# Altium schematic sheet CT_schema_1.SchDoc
size 550 x 508 mm
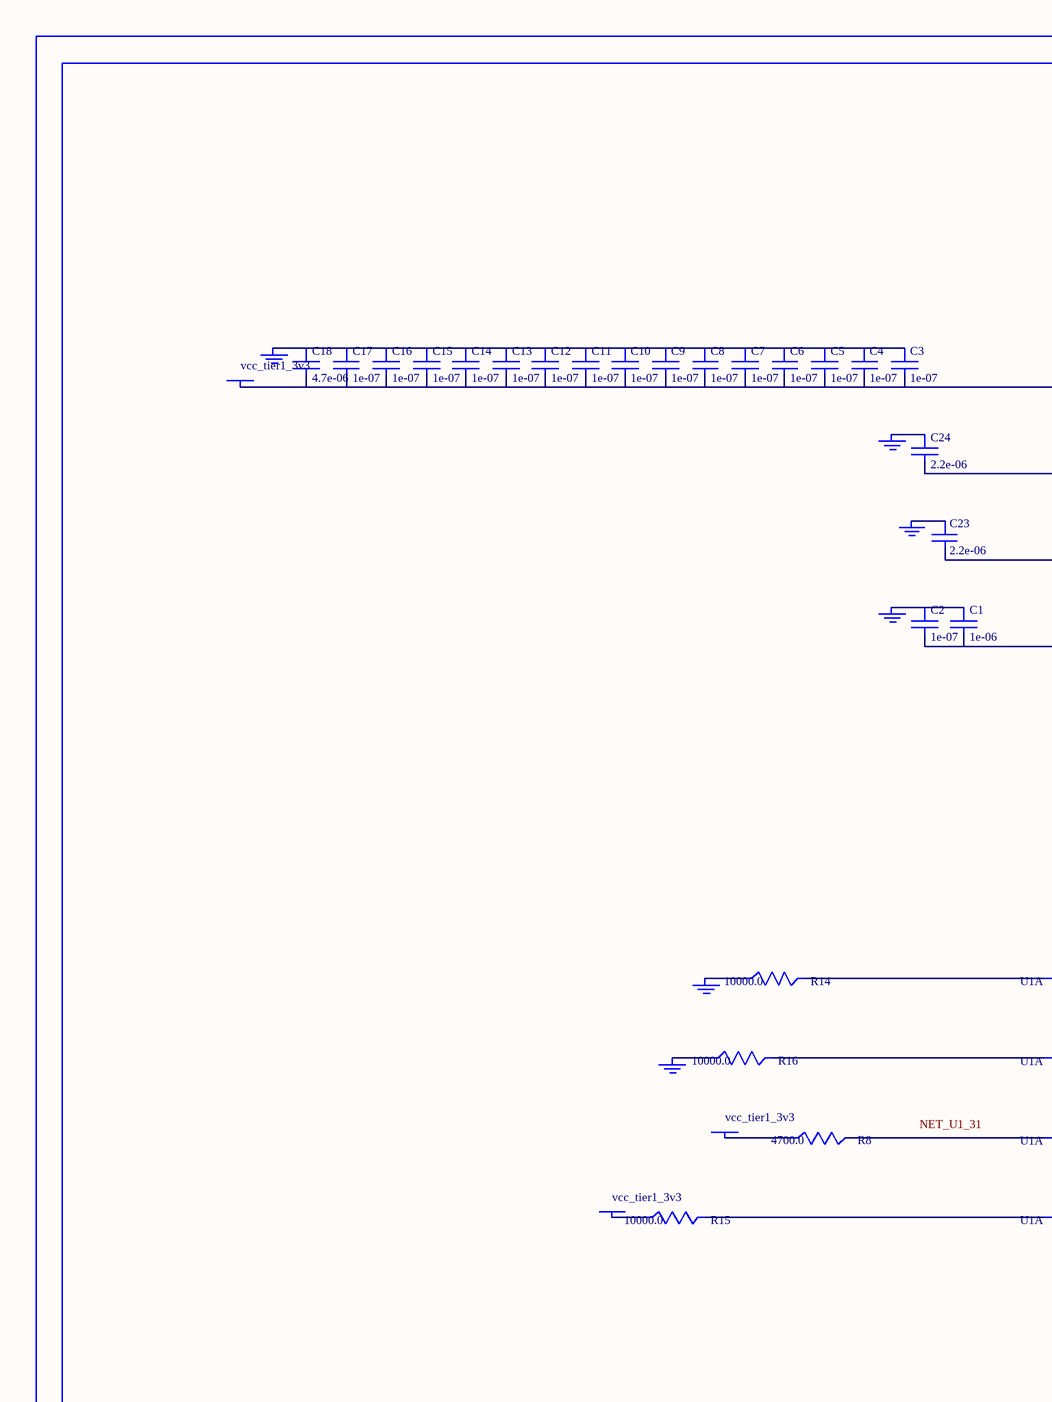
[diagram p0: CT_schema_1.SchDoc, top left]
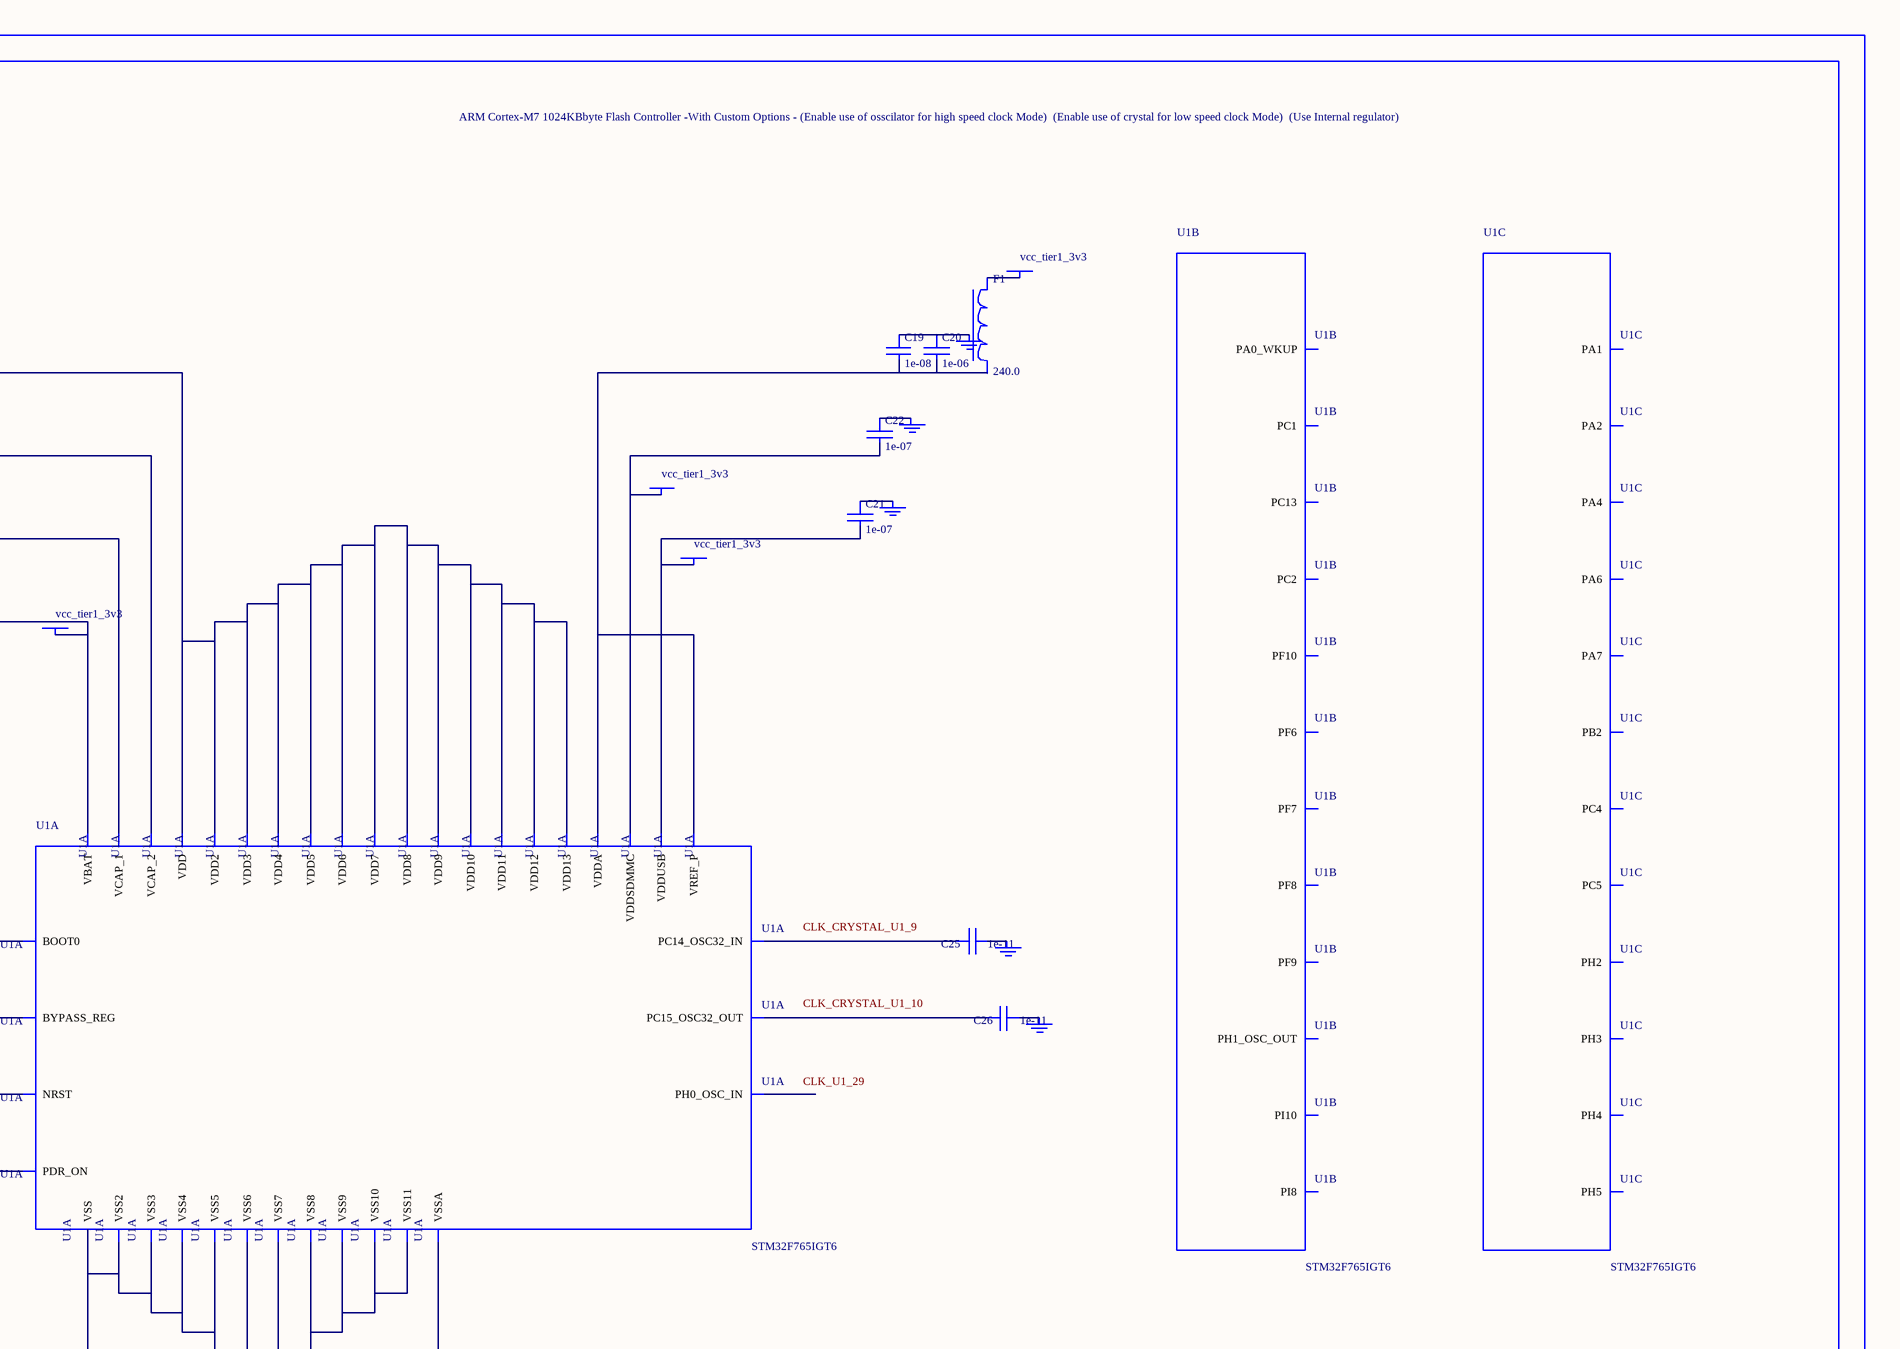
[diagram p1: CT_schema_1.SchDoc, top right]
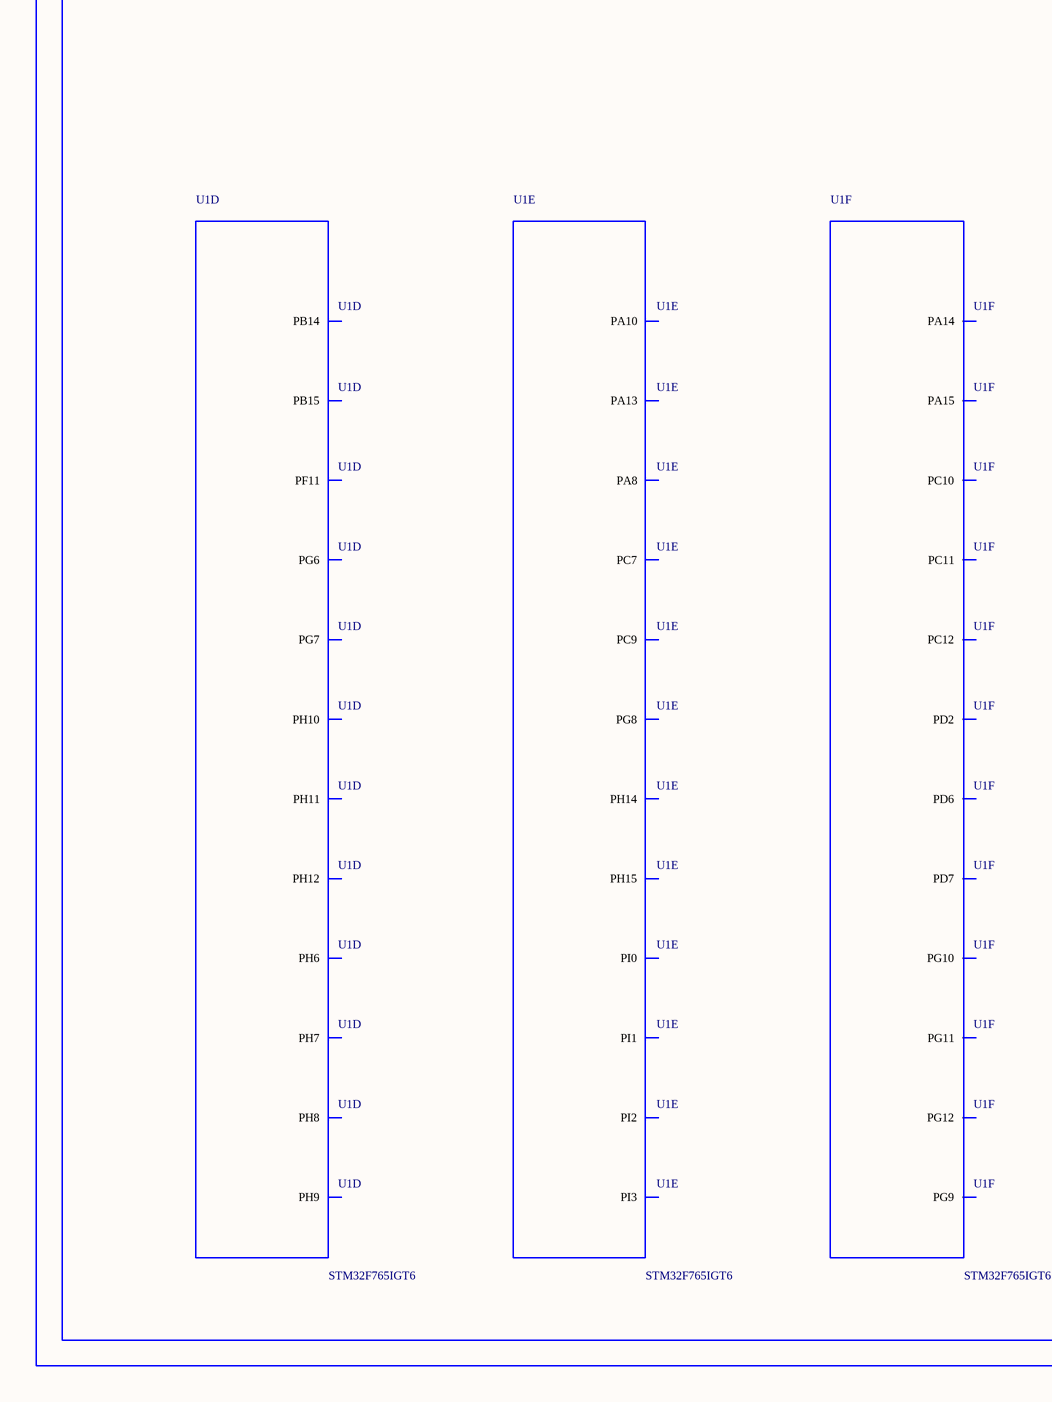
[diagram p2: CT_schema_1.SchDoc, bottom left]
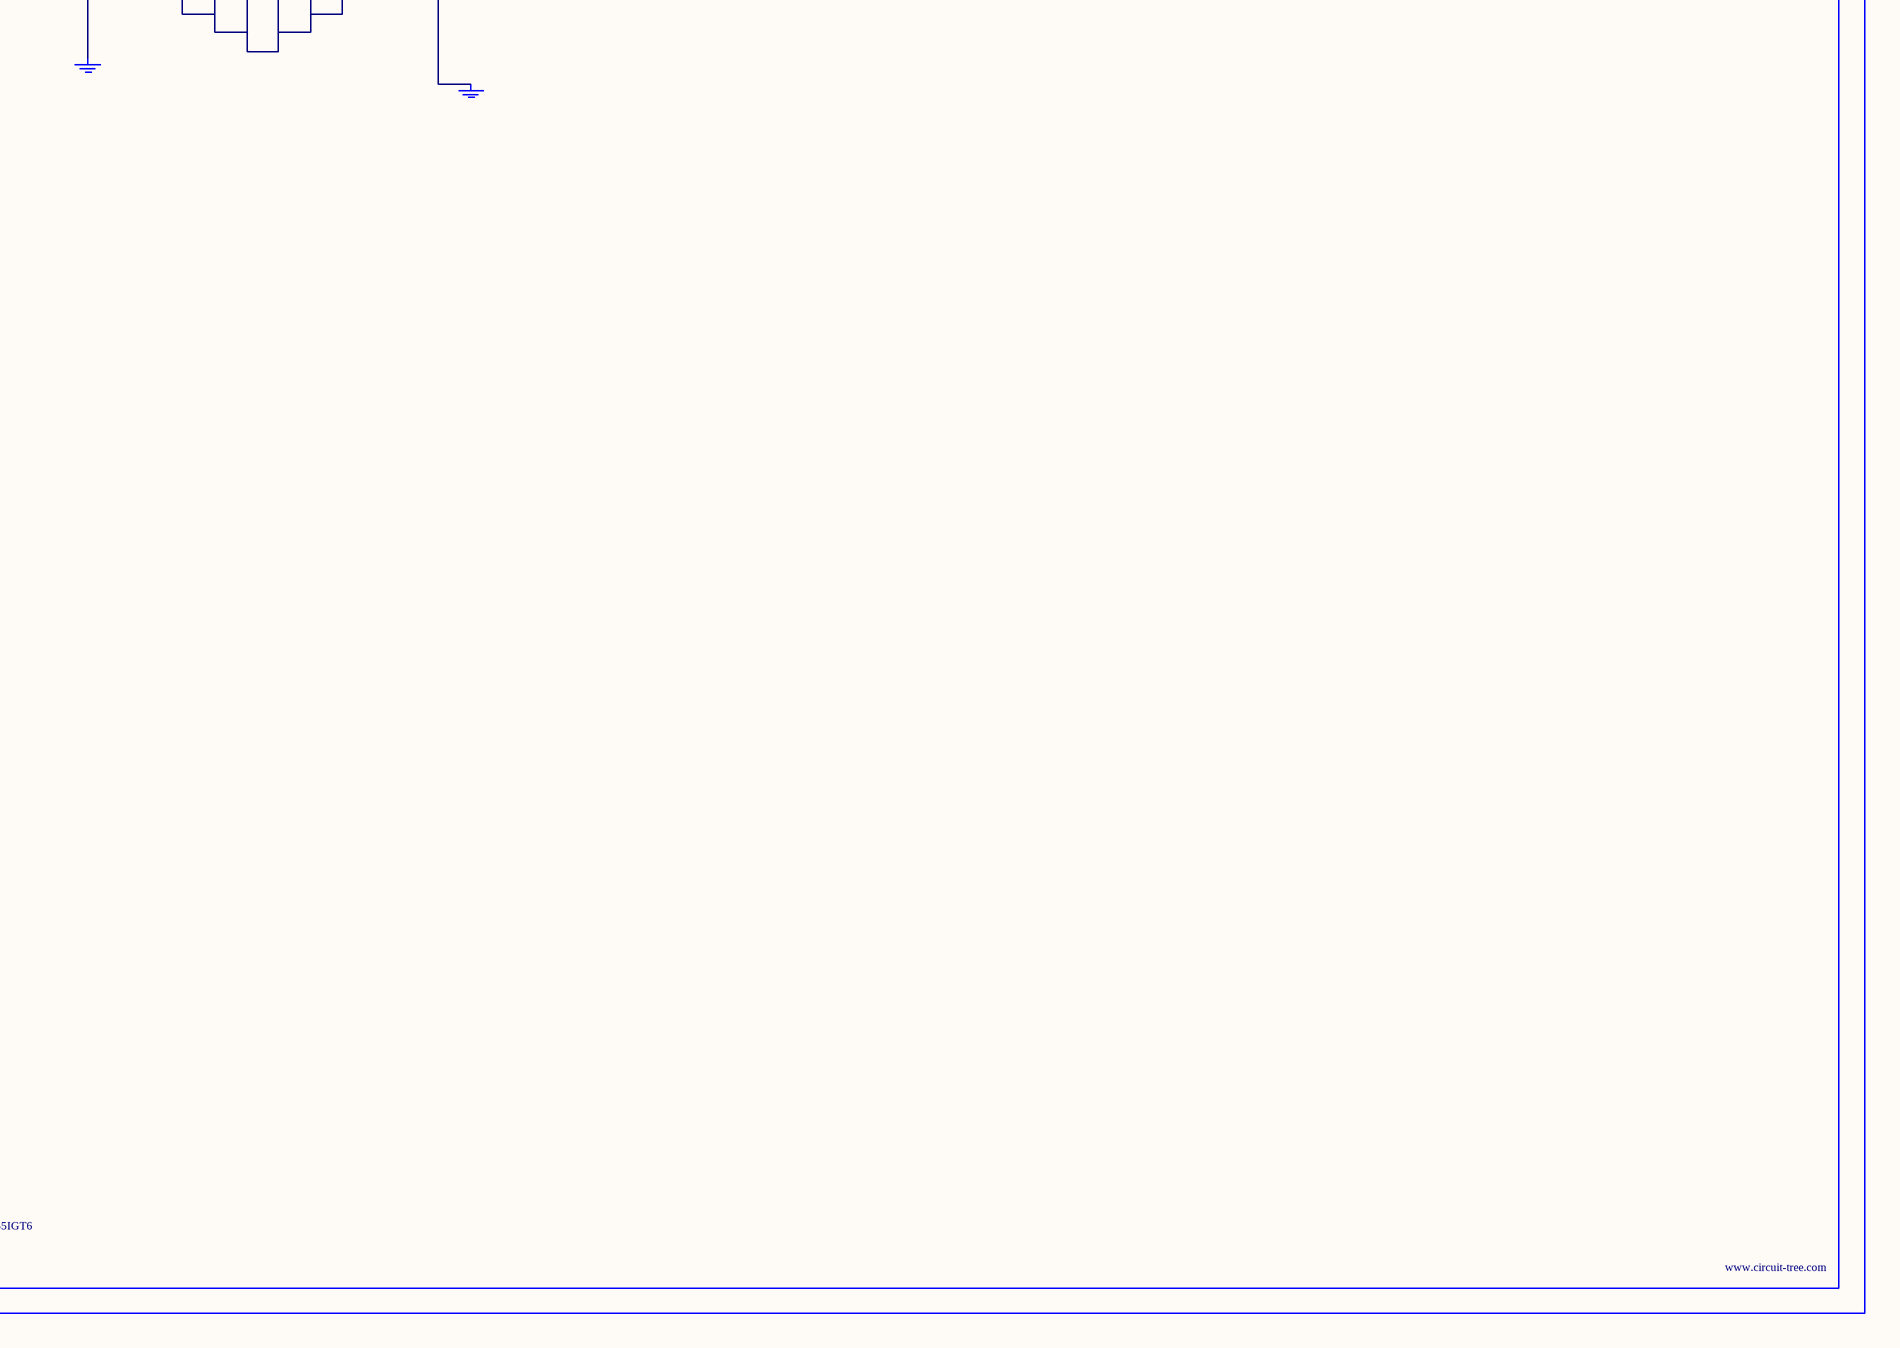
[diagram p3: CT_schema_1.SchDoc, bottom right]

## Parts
BORDER0  (no value)
C1  1e-06  [C0603]
C2  1e-07  [C0603]
C3  1e-07  [C0603]
C4  1e-07  [C0603]
C5  1e-07  [C0603]
C6  1e-07  [C0603]
C7  1e-07  [C0603]
C8  1e-07  [C0603]
C9  1e-07  [C0603]
C10  1e-07  [C0603]
C11  1e-07  [C0603]
C12  1e-07  [C0603]
C13  1e-07  [C0603]
C14  1e-07  [C0603]
C15  1e-07  [C0603]
C16  1e-07  [C0603]
C17  1e-07  [C0603]
C18  4.7e-06  [C0603]
C19  1e-08  [C0603]
C20  1e-06  [C0603]
C21  1e-07  [C0603]
C22  1e-07  [C0603]
C23  2.2e-06  [C0603]
C24  2.2e-06  [C0603]
C25  1e-11  [C0402]
C26  1e-11  [C0402]
F1  240.0  [L0603]
GND_INSTANCE_0_0  (no value)
GND_INSTANCE_0_1  (no value)
GND_INSTANCE_0_2  (no value)
GND_INSTANCE_0_3  (no value)
GND_INSTANCE_0_4  (no value)
GND_INSTANCE_0_5  (no value)
GND_INSTANCE_0_6  (no value)
GND_INSTANCE_0_7  (no value)
GND_INSTANCE_0_8  (no value)
GND_INSTANCE_0_9  (no value)
GND_INSTANCE_0_10  (no value)
GND_INSTANCE_0_11  (no value)
GND_INSTANCE_0_12  (no value)
POWER_INSTANCE_0_0  vcc_tier1_3v3
POWER_INSTANCE_0_1  vcc_tier1_3v3
POWER_INSTANCE_0_2  vcc_tier1_3v3
POWER_INSTANCE_0_3  vcc_tier1_3v3
POWER_INSTANCE_0_4  vcc_tier1_3v3
POWER_INSTANCE_0_5  vcc_tier1_3v3
POWER_INSTANCE_0_6  vcc_tier1_3v3
R8  4700.0  [R0603]
R14  10000.0  [R0603]
R15  10000.0  [R0603]
R16  10000.0  [R0603]
U1  STM32F765IGT6  [LQFP176]  (parts A,B,C,D,E,F of 14)

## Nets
NetC1_1: C1.1 C2.1 GND_INSTANCE_0_0.0(GND)
NetC1_2: C1.2 C2.2 POWER_INSTANCE_0_0.0(PWR) U1.6(VBAT)
NetC3_1: C3.1 C4.1 C5.1 C6.1 C7.1 C8.1 C9.1 C10.1 C11.1 C12.1 C13.1 C14.1 C15.1 C16.1 C17.1 C18.1 GND_INSTANCE_0_3.0(GND)
NetC3_2: C3.2 C4.2 C5.2 C6.2 C7.2 C8.2 C9.2 C10.2 C11.2 C12.2 C13.2 C14.2 C15.2 C16.2 C17.2 C18.2 POWER_INSTANCE_0_1.0(PWR) U1.15(VDD) U1.23(VDD2) U1.36(VDD3) U1.49(VDD4) U1.62(VDD5) U1.72(VDD6) U1.82(VDD7) U1.91(VDD8) U1.103(VDD9) U1.127(VDD10) U1.136(VDD11) U1.159(VDD12) U1.172(VDD13)
NetC19_1: C19.1 C20.1 GND_INSTANCE_0_5.0(GND)
NetC19_2: C19.2 C20.2 U1.38(VREF_P) U1.39(VDDA)
NetC21_1: C21.1 GND_INSTANCE_0_8.0(GND)
NetC21_2: C21.2 POWER_INSTANCE_0_3.0(PWR) U1.114(VDDUSB)
NetC22_1: C22.1 GND_INSTANCE_0_10.0(GND)
NetC22_2: C22.2 POWER_INSTANCE_0_4.0(PWR) U1.149(VDDSDMMC)
NetC23_1: C23.1 GND_INSTANCE_0_7.0(GND)
NetC23_2: C23.2 U1.81(VCAP_1)
NetC24_1: C24.1 GND_INSTANCE_0_9.0(GND)
NetC24_2: C24.2 U1.125(VCAP_2)
NetC25_1: C25.1 GND_INSTANCE_0_1.0(GND)
NetC25_2: C25.2 U1.9(PC14_OSC32_IN)
NetC26_1: C26.1 GND_INSTANCE_0_2.0(GND)
NetC26_2: C26.2 U1.10(PC15_OSC32_OUT)
NetF1_1: F1.1 POWER_INSTANCE_0_2.0(PWR)
NetGND_INSTANCE_0_4_0: GND_INSTANCE_0_4.0(GND) U1.37(VSSA)
NetGND_INSTANCE_0_6_0: GND_INSTANCE_0_6.0(GND) R16.1
NetGND_INSTANCE_0_11_0: GND_INSTANCE_0_11.0(GND) R14.1
NetGND_INSTANCE_0_12_0: GND_INSTANCE_0_12.0(GND) U1.14(VSS) U1.22(VSS2) U1.61(VSS3) U1.71(VSS4) U1.90(VSS5) U1.102(VSS6) U1.113(VSS7) U1.126(VSS8) U1.135(VSS9) U1.148(VSS10) U1.158(VSS11)
NetPOWER_INSTANCE_0_5_0: POWER_INSTANCE_0_5.0(PWR) R15.1
NetPOWER_INSTANCE_0_6_0: POWER_INSTANCE_0_6.0(PWR) R8.1
NetR8_2: R8.2 U1.31(NRST)
NetR14_2: R14.2 U1.166(BOOT0)
NetR15_2: R15.2 U1.171(PDR_ON)
NetR16_2: R16.2 U1.48(BYPASS_REG)

Not connected (* = marked no-connect by the designer): F1 2; U1 7(PI8) 8(PC13) 12(PI10) 24(PF6) 25(PF7) 26(PF8) 27(PF9) 28(PF10) 29(PH0_OSC_IN) 30(PH1_OSC_OUT) 33(PC1) 34(PC2) 40(PA0_WKUP) 41(PA1) 42(PA2) 43(PH2) 44(PH3) 45(PH4) 46(PH5) 50(PA4) 52(PA6) 53(PA7) 54(PC4) 55(PC5) 58(PB2) 59(PF11) 83(PH6) 84(PH7) 85(PH8) 86(PH9) 87(PH10) 88(PH11) 89(PH12) 94(PB14) 95(PB15) 110(PG6) 111(PG7) 112(PG8) 116(PC7) 118(PC9) 119(PA8) 121(PA10) 124(PA13) 129(PH14) 130(PH15) 131(PI0) 132(PI1) 133(PI2) 134(PI3) 137(PA14) 138(PA15) 139(PC10) 140(PC11) 141(PC12) 144(PD2) 150(PD6) 151(PD7) 152(PG9) 153(PG10) 154(PG11) 155(PG12)

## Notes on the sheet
- Labels drawn without touching a wire or pin: CLK_CRYSTAL_U1_9, CLK_CRYSTAL_U1_10, CLK_U1_29, NET_U1_31

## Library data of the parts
BORDER0 = BORDER_PAGE0
C1 C20 = C0603C105K3RACTU
C2-C17 C21 C22 = 06035C104K4Z2A
C18 = GRM188R6YA475KE15D
C19 = 06035C103K4Z2A
C23 C24 = C0603C225K8RACTU
C25 C26 = C0402C100K3GACTU
F1 = Z0603C241ASMST
GND_INSTANCE_0_0-GND_INSTANCE_0_12 = GND
POWER_INSTANCE_0_0-POWER_INSTANCE_0_6 = PWR
R8 = RC0603JR-074K7L
R14-R16 = RC0603JR-0710KL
